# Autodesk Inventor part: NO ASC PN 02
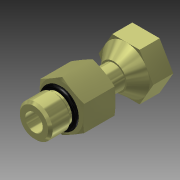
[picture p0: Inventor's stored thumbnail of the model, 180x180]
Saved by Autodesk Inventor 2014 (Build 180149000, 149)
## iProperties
Shininess: 20.0
Length Units: 11272
Angle Units: 11279
Time Units: 11290
Mass Units: 11286
Length Display Precision: 3
Angle Display Precision: 2
Company: Autodesk, Inc.
Created: 2001-12
Part Number: NO ASC PN 02
Material: Steel, Mild A-36
Description: FITTING; ST-A9G6-S
Document SubType Name: Modeling
Designer: Autodesk, Inc.
Density: 8.182 g/cm^3
Appearance: Yellow Zinc
Density: 7.86
Volumn: 5.818506058552819
Area: 35.84085697721723
PropertySet Name: Model Information
Control State: 0
Master: False
Checked Out: False
Last Check In By: JT
Last Check In Date: 2003-06-20
MODEL - 1: ---
MODEL - 2: ---
RAW MATERIAL: --------
SCALE:: 1=??
SIZE: 00 x 00 x 00
SUB-ASSY - 1: ------
SUB-ASSY - 1 - QUA: 1
SUB-ASSY - 2: ------
SUB-ASSY - 2 - QUA: 1
SYM. TO:: N/A
TEMPLATE CREATION: -- / __-__-__
Title: FITTING; ST-A9G6-S
Author: Autodesk, Inc.
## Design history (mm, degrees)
sketch "Sketch1"
  geometry: L1 (0, 10.999)-(9.525, 5.499); L2 (9.525, 5.499)-(9.525, -5.499); L3 (9.525, -5.499)-(0, -10.999); L4 (0, -10.999)-(-9.525, -5.499); L5 (-9.525, -5.499)-(-9.525, 5.499); L6 (-9.525, 5.499)-(0, 10.999); C1 r 3.823 at (0, 0); 2 further points
  constraints: 12 end point, 2 coincident, 1 centre point, 1 vertical alignment, 11 other
  dimensions: "d3" = 19.05 distance between parallel lines of L4 L1 (= Hex_Size); "d42" = 7.6454 diameter of C1 (= Oring_ID)
extrude "Hex Nut Extrusion" new body sketch "Sketch1" distance "d4" = 14.097 (= L5 - BB - CC); taper "d5" = 0 deg
sketch "Sketch2"
  geometry: L1 (4.912, 0)-(19.05, 0); L2 (4.825, 14.097)-(14.86, 14.097); L3 (9.525, 14.097)-(9.525, 0); L4 (0, 0)-(0, 27.779); L5 (9.525, 0)-(19.05, 2.552); L6 (9.525, 14.097)-(19.05, 11.545); L7 (9.525, 0)-(10.745, 0); L8 (19.05, 14.097)-(9.525, 14.097); L9 (19.05, 0)-(19.05, 2.552); L10 (19.05, 11.545)-(19.05, 14.097); L11 (9.525, 0)-(19.05, 0)
  constraints: 22 end point, 6 perpendicular, 5 point on line, 2 parallel, 1 collinear, 1 horizontal
  dimensions: "d6" = 14.097 distance between parallel lines of L2 L1 (= L5 - BB - CC); "d7" = 19.05 diameter of L3 L4 (= Hex_Size); "d8" = 15 deg angle of L1 L5; "d9" = 15 deg angle of L2 L6; "d10" = 9.525 distance between parallel lines of L10 L3
revolve "Hex Nut Chamfer" sketch "Sketch2" stored, may be unused: angle "d11" = 90 deg
sketch "Sketch3"
  geometry: L1 (0, -19.521)-(0, 19.521); L2 (-8.249, 0)-(0, 0) reference; L3 (8.249, 14.097)-(0, 14.097) reference; L4 (0, 14.097)-(-8.249, 14.097) reference; L5 (9.525, 14.097)-(8.249, 14.097) reference; L6 (-8.249, 14.097)-(-9.525, 14.097) reference; L7 (-9.525, 0)-(-8.249, 0) reference; L8 (6.147, 14.097)-(6.147, 16.586); L9 (6.147, 16.586)-(7.144, 17.583); L10 (7.144, 17.583)-(7.144, 25.051); L11 (7.144, 25.051)-(6.159, 26.035); L12 (6.159, 26.035)-(3.823, 26.035); L13 (3.823, 26.035)-(3.823, 14.097); L14 (3.823, 14.097)-(6.147, 14.097); L15 (0, 0)-(5.029, 0); L16 (5.029, 0)-(5.029, -8.731); L17 (5.029, -8.731)-(5.7, -8.731); L18 (5.7, -8.731)-(10.319, -14.097); L19 (10.319, -14.097)-(10.319, -22.828); L20 (10.319, -22.828)-(8.731, -22.828); L21 (8.731, -22.828)-(8.731, -14.097); L22 (8.731, -14.097)-(3.353, -14.097); L23 (3.353, -14.097)-(3.353, 0)
  constraints: 34 end point, 9 perpendicular, 4 parallel, 3 point on line, 1 collinear, 1 horizontal alignment, 1 midpoint, 1 vertical
  dimensions: "d22" = 2.4892 distance of L8.start L8.end (= Oring_Undercut_Length_H); "d23" = 11.938 distance between parallel lines of L12 L3 (= BB); "d24" = 12.2936 diameter of L8 L1 (= Oring_Undercut_G1); "d25" = 12.319 diameter of L11.end L1 (= Oring_Lip); "d26" = 7.6454 diameter of L13 L1 (= Oring_ID); "d27" = 14.2875 diameter of L10 L1 (= Oring_Thread_OD); "d43" = 45 deg angle of L10 L11; "d45" = 6.7056 diameter of L23 L1 (= D1); "d46" = 28.194 distance between parallel lines of L22 L3 (= HHH); "d47" = 17.4625 diameter of L21 L1 (= T6); "d48" = 20.6375 diameter of L19 L1 (= B); "d49" = 8.73125 distance of L20.end L21.end (= 0.5 x T6); "d50" = 14.097 distance between parallel lines of L20 L17 (= HHH - d4); "d52" = 10.0584 diameter of L16 L1 (= 1.5 x D1); "d59" = 0.67056 distance of L16.end L17.end (= 0.1 x D1)
revolve "Oring Face_Seal Revolution" sketch "Sketch3" stored, may be unused: angle "d28" = 90 deg
sketch "Sketch4"
  geometry: L1 (0, -12.403)-(0, 13.958); C1 r 1.029 at (7.176, 15.126); 2 further points
  constraints: 2 end point, 1 centre point, 1 coincident, 1 point on line, 1 vertical
  dimensions: "d34" = 2.0574 diameter of C1 (= Oring_Seal); "d35" = 14.351 diameter of C1.centre L1 (= Oring_Undercut_G1 + Oring_Seal); "d36" = 15.1257 vertical distance of C1.centre point (0, 0) (= -CC - BB + L5 + 0.5 x Oring_Seal)
revolve "Orings" sketch "Sketch4" stored, may be unused: angle "d39" = 90 deg
sketch "Sketch6"
  geometry: L1 (11.915, 0)-(5.958, -10.319); L2 (5.958, -10.319)-(-5.958, -10.319); L3 (-5.958, -10.319)-(-11.915, 0); L4 (-11.915, 0)-(-5.958, 10.319); L5 (-5.958, 10.319)-(5.958, 10.319); L6 (5.958, 10.319)-(11.915, 0); C1 r 10.319 at (0, 0) reference; 1 further point
  constraints: 12 end point, 1 coincident, 1 horizontal, 11 other
  dimensions: "d54" = 20.6375 distance between parallel lines of L3 L6 (= B)
extrude "Extrusion4" join sketch "Sketch6" distance "d56" = 8.73125 (= d49); taper "d57" = 0 deg
body "Solid1"
other parameters: "Hex_Size" = 19.05 [user parameter; used in 2 equation terms], "L5" = 40.132 [user parameter; used in 3 equation terms], "CC" = 14.097 [user parameter; used in 3 equation terms], "BB" = 11.938 [user parameter; used in 4 equation terms], "Face_Seal_ID" = 6.604 [user parameter], "Oring_Undercut_Length_H" = 2.4892 [user parameter; used in 1 equation term], "Oring_Undercut_G1" = 12.2936 [user parameter; used in 2 equation terms], "Oring_Thread_OD" = 14.2875 [user parameter; used in 1 equation term], "Oring_Lip" = 12.319 [user parameter; used in 1 equation term], "Oring_ID" = 7.6454 [user parameter; used in 2 equation terms], "Oring_Seal" = 2.0574 [user parameter; used in 3 equation terms], "D1" = 6.7056 [user parameter; used in 3 equation terms], "HHH" = 28.194 [user parameter; used in 2 equation terms], "T6" = 17.4625 [user parameter; used in 2 equation terms], "B" = 20.6375 [user parameter; used in 2 equation terms]
